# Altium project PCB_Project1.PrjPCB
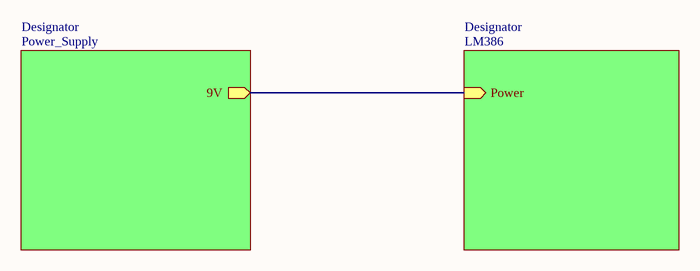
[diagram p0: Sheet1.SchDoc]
3 sheets, 38 parts. Net scope: hierarchical (ports join the sheet entries above them; power ports are global).
Sheets:
  Sheet1.SchDoc
    Designator = Power_Supply.SchDoc
    Designator = LM386.SchDoc

## Sheet Sheet1.SchDoc
size A4

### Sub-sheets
Designator = Power_Supply: 9V (out)
Designator = LM386: Power (in)

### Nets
NetC11_2: sheet Designator/9V, sheet Designator/Power

## Sheet Power_Supply.SchDoc
size A4
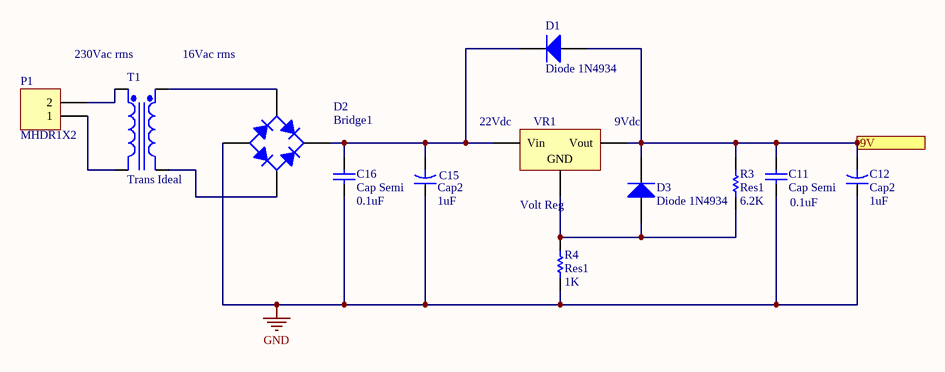
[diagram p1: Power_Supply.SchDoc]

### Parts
C11  Cap Semi  value 0.1uF  [C1206]
C12  Cap2  value 1uF  [CAPR5-4X5]
C15  Cap2  value 1uF  [CAPR5-4X5]
C16  Cap Semi  value 0.1uF  [C1206]
D1  Diode 1N4934  [DO-41]
D2  Bridge1  [D-38]
D3  Diode 1N4934  [DO-41]
P1  MHDR1X2  [MHDR1X2]
R3  Res1  value 6.2K  [AXIAL-0.3]
R4  Res1  value 1K  [AXIAL-0.3]
T1  Trans Ideal  [TRF_4]
VR1  Volt Reg  [D2PAK_N]

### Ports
9V (out)

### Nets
GND: C11.1 C12.1 C15.1 C16.1 D2.3(A) R4.1
NetC11_2: C11.2 C12.2 D1.1(A) D3.2(K) R3.1 VR1.3(Vout) ; port 9V
NetC15_2: C15.2 C16.2 D1.2(K) D2.1(K) VR1.1(Vin)
NetD2_2: D2.2(C) T1.4(Sec-)
NetD2_4: D2.4(C) T1.3(Sec+)
NetD3_1: D3.1(A) R3.2 R4.2 VR1.2(GND)
NetP1_1: P1.1 T1.2(Pri-)
NetP1_2: P1.2 T1.1(Pri+)

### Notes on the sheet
- 230Vac rms
- 16Vac rms
- (near VR1) 22Vdc
- (near VR1) 9Vdc

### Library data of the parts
C11 C16 = Cap Semi: Capacitor (Semiconductor SIM Model)
C12 C15 = Cap2: Capacitor
D1 D3 = Diode 1N4934: 1 Amp Fast Recovery Rectifier
D2 = Bridge1: Full Wave Diode Bridge
P1 = MHDR1X2: Header, 2-Pin
R3 R4 = Res1: Resistor
T1 = Trans Ideal: Transformer (Ideal)
VR1 = Volt Reg: Voltage Regulator

## Sheet LM386.SchDoc
size A4
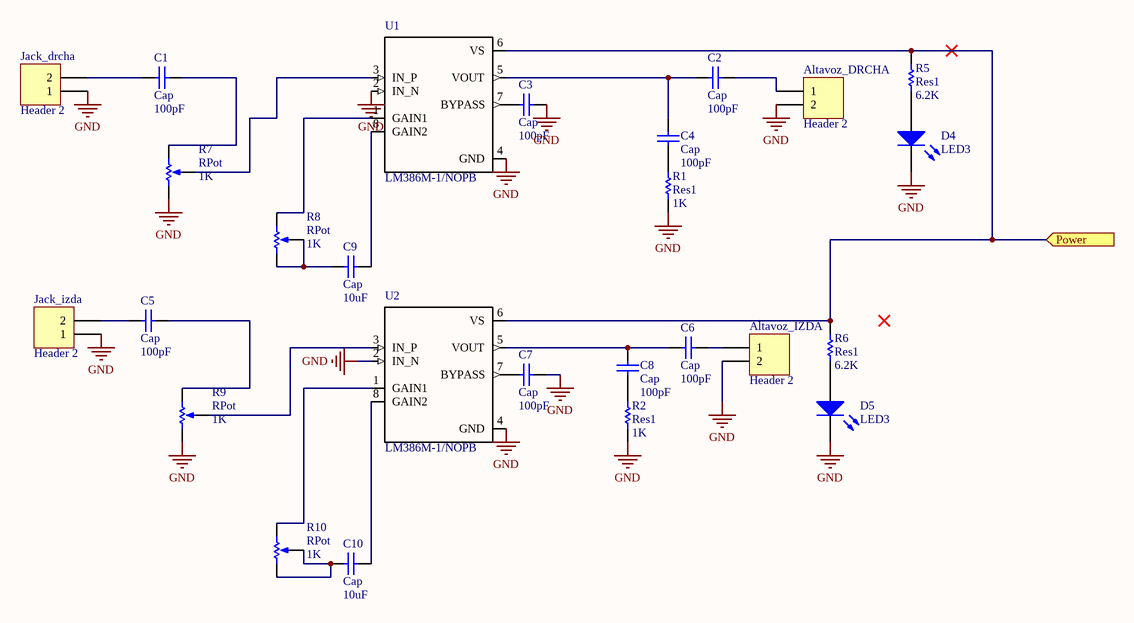
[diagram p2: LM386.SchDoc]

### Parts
Altavoz_DRCHA  Header 2  [HDR1X2]
Altavoz_IZDA  Header 2  [HDR1X2]
C1  Cap  value 100pF  [RAD-0.3]
C2  Cap  value 100pF  [RAD-0.3]
C3  Cap  value 100pF  [RAD-0.3]
C4  Cap  value 100pF  [RAD-0.3]
C5  Cap  value 100pF  [RAD-0.3]
C6  Cap  value 100pF  [RAD-0.3]
C7  Cap  value 100pF  [RAD-0.3]
C8  Cap  value 100pF  [RAD-0.3]
C9  Cap  value 10uF  [RAD-0.3]
C10  Cap  value 10uF  [RAD-0.3]
D4  LED3  [3.5X2.8X1.9]
D5  LED3  [3.5X2.8X1.9]
Jack_drcha  Header 2  [HDR1X2]
Jack_izda  Header 2  [HDR1X2]
R1  Res1  value 1K  [AXIAL-0.3]
R2  Res1  value 1K  [AXIAL-0.3]
R5  Res1  value 6.2K  [AXIAL-0.3]
R6  Res1  value 6.2K  [AXIAL-0.3]
R7  RPot  value 1K  [SOIC127P600X175-8N]
R8  RPot  value 1K  [VR5]
R9  RPot  value 1K  [VR5]
R10  RPot  value 1K  [VR5]
U1  LM386M-1/NOPB  [SOIC127P600X175-8N]
U2  LM386M-1/NOPB  [SOIC127P600X175-8N]

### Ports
Power (in)

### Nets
GND: Altavoz_DRCHA.2 Altavoz_IZDA.2 C3.1 C7.2 D4.2(K) D5.2(K) Jack_drcha.1 Jack_izda.1 R1.1 R2.1 R7.1(TOP) R9.1(TOP) U1.2(IN_N) U1.4(GND) U2.2(IN_N) U2.4(GND)
NetAltavoz_DRCHA_1: Altavoz_DRCHA.1 C2.2
NetAltavoz_IZDA_1: Altavoz_IZDA.1 C6.2
NetC1_1: C1.1 R7.2(BOT)
NetC1_2: C1.2 Jack_drcha.2
NetC2_1: C2.1 C4.2 U1.5(VOUT)
NetC3_2: C3.2 U1.7(BYPASS)
NetC4_1: C4.1 R1.2
NetC5_1: C5.1 R9.2(BOT)
NetC5_2: C5.2 Jack_izda.2
NetC6_1: C6.1 C8.2 U2.5(VOUT)
NetC7_1: C7.1 U2.7(BYPASS)
NetC8_1: C8.1 R2.2
NetC9_1: C9.1 U1.8(GAIN2)
NetC9_2: C9.2 R8.1(TOP) R8.3(TAP)
NetC10_1: C10.1 U2.8(GAIN2)
NetC10_2: C10.2 R10.1(TOP) R10.3(TAP)
NetC11_2: R5.1 R6.1 U1.6(VS) U2.6(VS) ; port Power
NetD4_1: D4.1(A) R5.2
NetD5_1: D5.1(A) R6.2
NetR7_3: R7.3(TAP) U1.3(IN_P)
NetR8_2: R8.2(BOT) U1.1(GAIN1)
NetR9_3: R9.3(TAP) U2.3(IN_P)
NetR10_2: R10.2(BOT) U2.1(GAIN1)

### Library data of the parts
Altavoz_DRCHA Altavoz_IZDA Jack_drcha Jack_izda = Header 2: Header, 2-Pin
C1-C10 = Cap: Capacitor
D4 D5 = LED3: Typical BLUE SiC LED
R1 R2 R5 R6 = Res1: Resistor
R7-R10 = RPot: Potentiometer; Sim Note: Enter the Resistance value and the set point into parameter fields.; Set Position: 0.5
U1 U2 = LM386M-1/NOPB: Wide Input Voltage Low Power Audio Amplifier with Internal Gain 8-SOIC 0 to 70; MF: Texas Instruments

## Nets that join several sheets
GND: Power_Supply (6 pins), LM386 (16 pins)
NetC11_2: Power_Supply (6 pins), LM386 (R5.1 R6.1 U1.6 U2.6)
